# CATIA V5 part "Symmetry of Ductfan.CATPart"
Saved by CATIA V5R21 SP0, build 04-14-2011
Part number: Symmetry of Ductfan
Bounding box of the stored display mesh (mm): x -344.98 to 394.667, y -360 to 40, z -344.802 to 344.802
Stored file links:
  C:\Users\rodri\OneDrive\Área de Trabalho\FACULDADE\3°semestre\Sistemas Aeroespaciais\Projeto de avião 2019-02\CAD\Symmetry of Ductfan.CATPart
  C:\Users\rodri\OneDrive\Área de Trabalho\FACULDADE\3°semestre\Sistemas Aeroespaciais\Projeto de avião 2019-02\CAD\Ductfan completo.CATPart
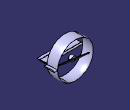
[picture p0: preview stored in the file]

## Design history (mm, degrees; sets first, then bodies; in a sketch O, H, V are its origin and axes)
Body1 (main body)
  Body2 "Body from original PartBody"
    Solid1: linked copy from another document
  Assemble1: tool Body2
